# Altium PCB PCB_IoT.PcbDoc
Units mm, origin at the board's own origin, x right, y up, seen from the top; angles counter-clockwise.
Board outline 99 x 58 mm, 2 copper layers (Top Layer, Bottom Layer); 42 components, 35 nets, 208 pads, 0 vias.
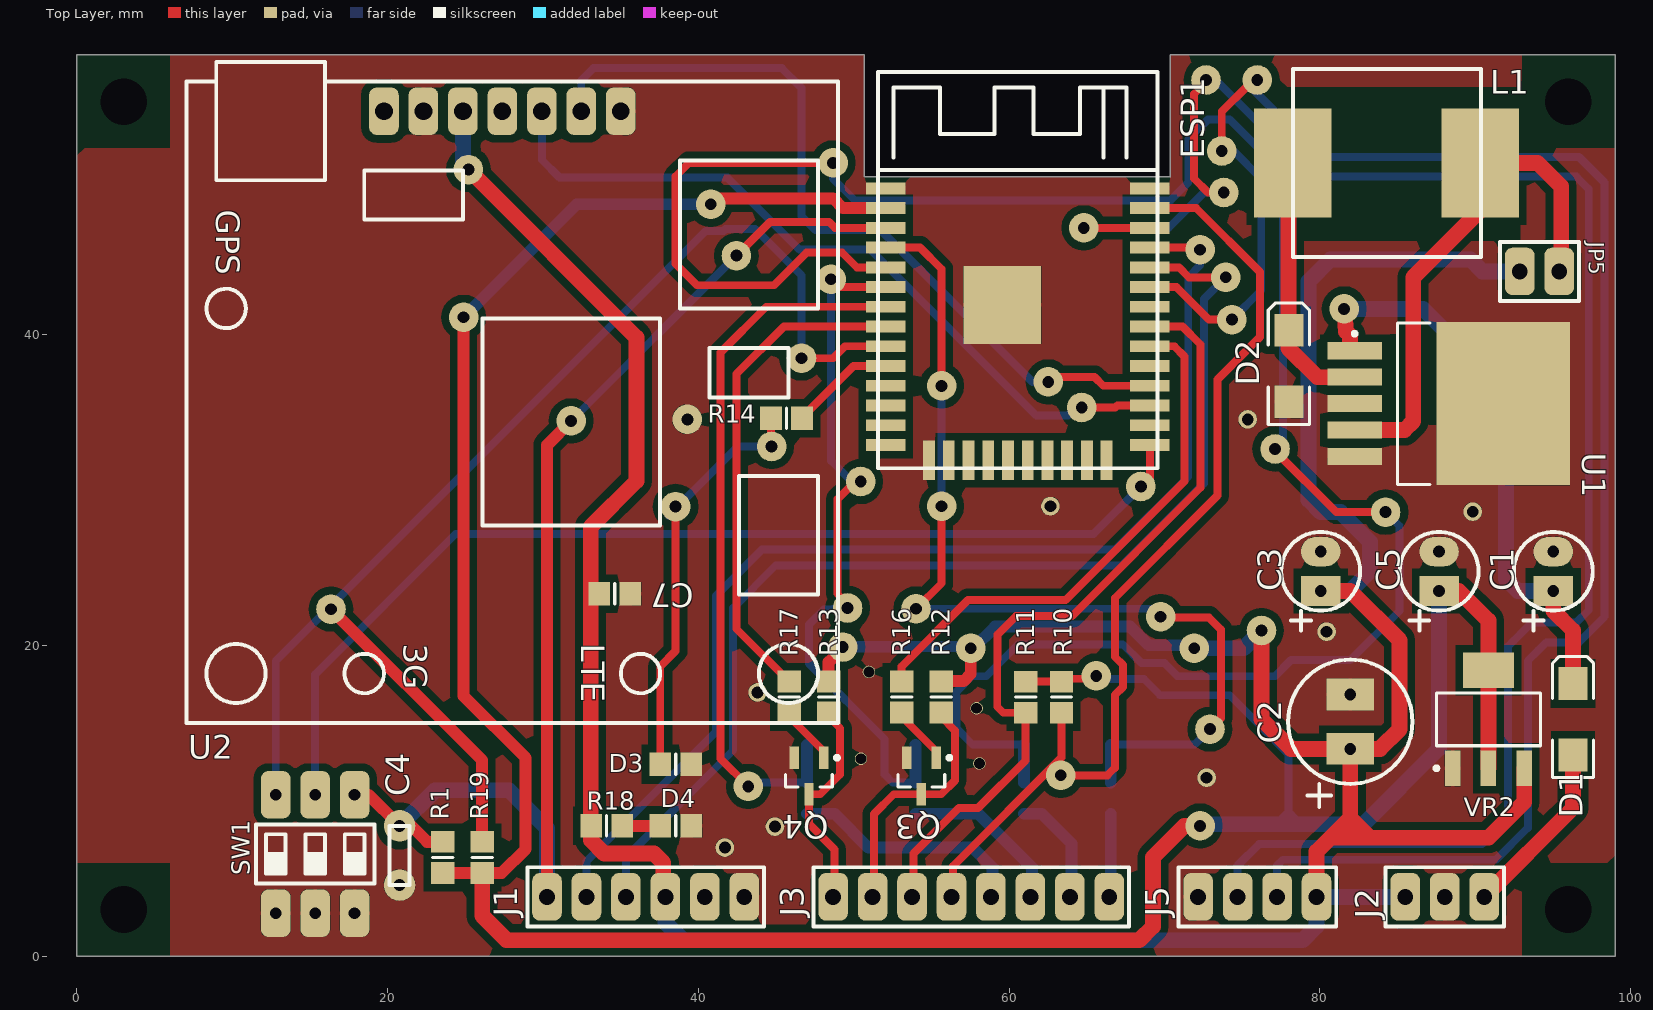
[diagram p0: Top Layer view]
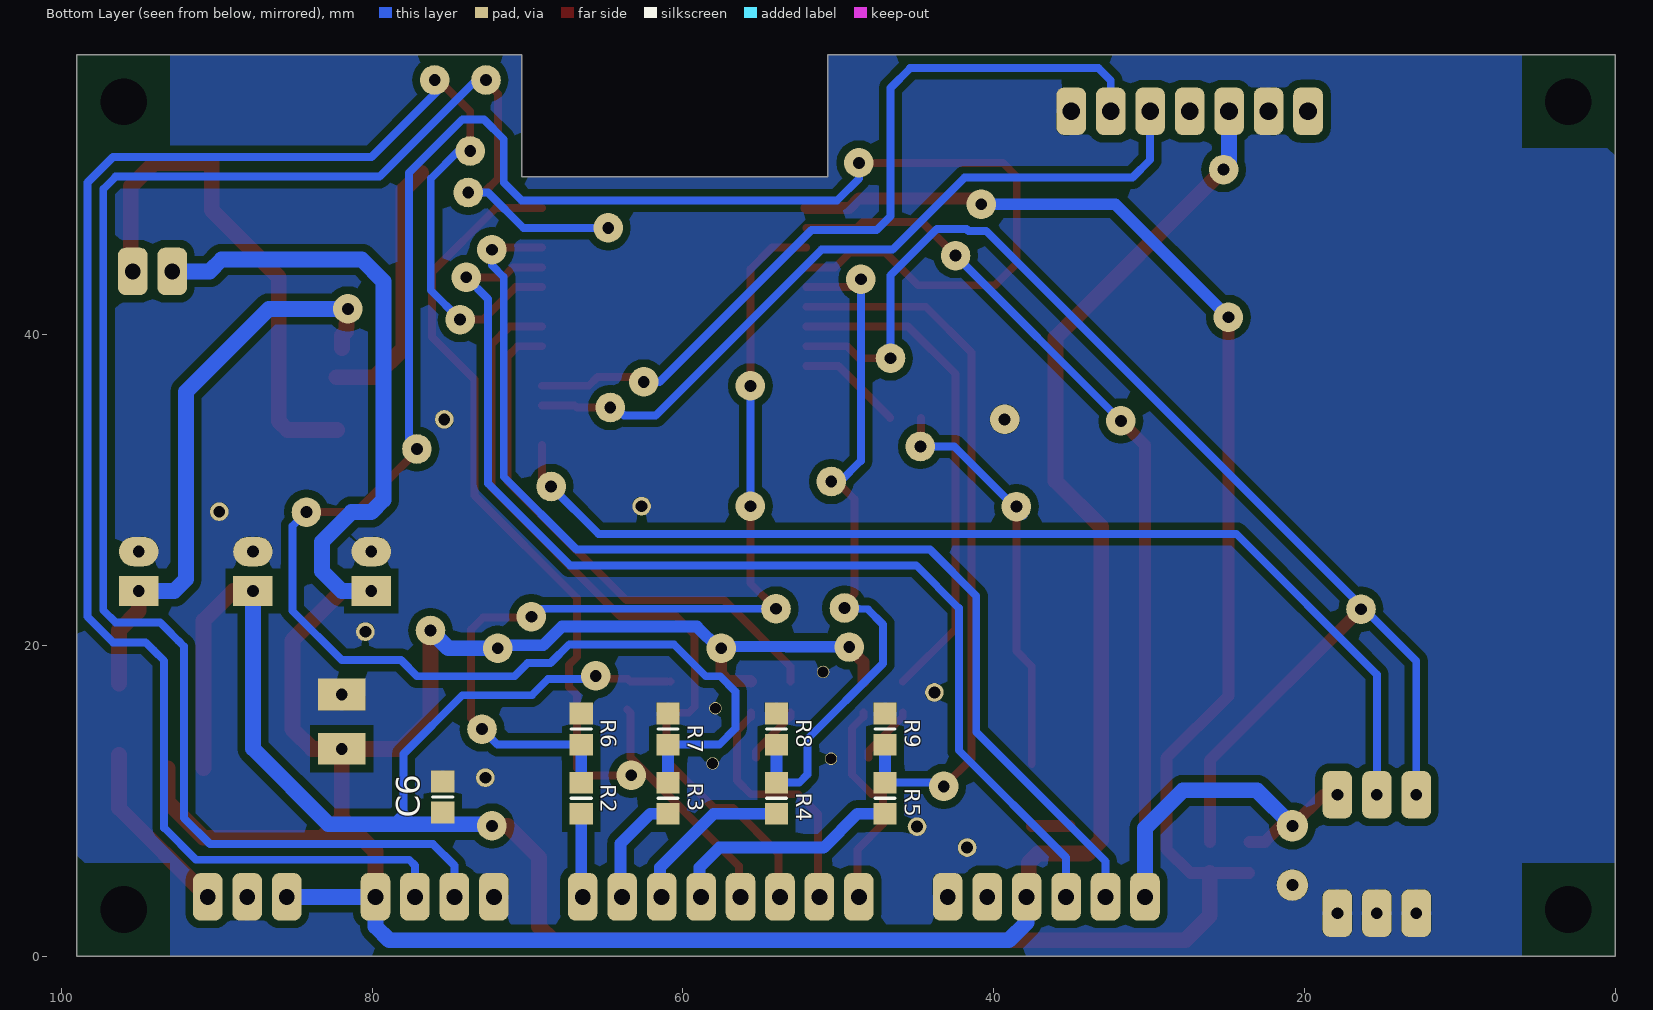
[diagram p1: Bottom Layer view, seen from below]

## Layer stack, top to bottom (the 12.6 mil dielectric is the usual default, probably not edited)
Top Solder: solder mask 0.0102, Solder Resist, Dk 3.5
Top Layer: signal copper 0.0356
Dielectric 1: dielectric 0.32, FR-4, Dk 4.8
Bottom Layer: signal copper 0.0356
Bottom Solder: solder mask 0.0102, Solder Resist, Dk 3.5

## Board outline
0,0 0,58 50.67,58 50.67,50.165 70.355,50.165 70.355,58 99,58 99,0

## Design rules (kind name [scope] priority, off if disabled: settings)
Clearance Clearance_4 [InNamedPolygon('GND_BOTTOM')] p1: gap=0.5 ignorepadtopadclearanceinfootprint=FALSE
Clearance Clearance_3 [InNamedPolygon('GND_TOP')] p2: gap=0.5 ignorepadtopadclearanceinfootprint=FALSE
Clearance Clearance_2 [InNamedPolygon('GND_BOTTOM')] p3: gap=0.5 ignorepadtopadclearanceinfootprint=FALSE
Clearance Clearance_1 [InNamedPolygon('GND_TOP')] p4: gap=0.5 ignorepadtopadclearanceinfootprint=FALSE
Clearance [All] p5: gap=0.508 ignorepadtopadclearanceinfootprint=FALSE
HoleSize [All] p1: absolutevalues=TRUE maxlimit=4 minlimit=0.025 maxpercent=80.000 minpercent=20.000
PolygonConnect PolygonConnect_4 [All vs IsNamedPolygon('GND_BOTTOM')] p1: connectstyle=Relief reliefconductorwidth=0.254 reliefentries=4 polygonreliefangle="90 Angle" airgapwidth=0
PolygonConnect PolygonConnect_3 [All vs IsNamedPolygon('GND_TOP')] p2: connectstyle=Relief reliefconductorwidth=0.254 reliefentries=4 polygonreliefangle="90 Angle" airgapwidth=0
PolygonConnect PolygonConnect_2 [All vs IsNamedPolygon('GND_BOTTOM')] p3: connectstyle=Relief reliefconductorwidth=0.254 reliefentries=4 polygonreliefangle="90 Angle" airgapwidth=0
PolygonConnect PolygonConnect_1 [All vs IsNamedPolygon('GND_TOP')] p4: connectstyle=Relief reliefconductorwidth=0.254 reliefentries=4 polygonreliefangle="90 Angle" airgapwidth=0
PolygonConnect [All] p5: connectstyle=Relief reliefconductorwidth=0.254 reliefentries=4 polygonreliefangle="90 Angle" airgapwidth=0.254
RoutingVias [All] p1: holewidth=0.711 width=1.27 viastyle="Through Hole" minholewidth=0.711 minwidth=1.27 maxholewidth=0.711 maxwidth=1.27
SilkToSilkClearance [All] p1 off: silktosilkclearance=0.254
SilkToSolderMaskClearance [IsPad] p1 off: minsilkscreentomaskgap=0.254 clearancetoexposedcopper=TRUE
SolderMaskExpansion [All] p1: expansion=0.102 istentingtop=FALSE
Width [All] p1: maxlimit=1.016 minlimit=0.508 preferedwidth=0.762
27 further rules are at their usual default settings.

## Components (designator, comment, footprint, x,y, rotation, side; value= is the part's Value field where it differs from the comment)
C1 "CAP_ELEC" CAP_ELEC_1 95.025,23.495 r90 top value=100uF/35V
C2 "CAP_ELEC" CAP_ELEC_3.5MM 81.96,13.335 r90 top value=220uF/35V
C3 "CAP_ELEC" CAP_ELEC_1 80.055,23.495 r90 top value=100uF/35V
C4 "Cap" CAP 20.765,4.57 r90 top value=100nF
C5 "Cap2" CAP_ELEC_1 87.675,23.495 r90 top value=100uF/35V
C6 "Cap" 6-0805_M 75.458,10.236 r270 bottom value=100nF
C7 "Cap" 6-0805_M 34.614,23.317 r180 top value=100nF
D1 "Diode 1N4007" DO214 96.295,15.24 r90 top
D2 "1N5822" DO214 78.007,37.973 r90 top
D3 "LED0" 6-0805_M 38.541,12.344 r0 top
D4 "LED0" 6-0805_M 38.541,8.382 r0 top
ESP1 "ESP-WROOM-32" ESP32-WROOM-32D 59.56,41.91 r0 top
J1 "SIL_6" SIL_6 42.955,3.81 r180 top
J2 "SIL_3" SIL_3 90.58,3.81 r180 top
J3 "SIL_8" SIL_8 66.45,3.81 r180 top
J5 "SIL_4" SIL_4 79.785,3.81 r180 top
JP5 "JUMPER" SIL_2 95.406,44.069 r180 top
L1 "Inductor" INDUTOR_SMD 78.261,51.054 r0 top value=33uH
Q3 "BC817-25" SOT-23A_M 54.353,11.589 r270 top
Q4 "BC817-25" SOT-23A_M 47.114,11.589 r270 top
R1 "Res1" 6-0805_M 23.54,6.35 r270 top value=22k
R2 "Res1" 6-0805_M 66.545,10.16 r270 bottom value=0R
R3 "Res1" 6-0805_M 60.957,10.16 r270 bottom value=0R
R4 "Res1" 6-0805_M 53.972,10.16 r270 bottom value=0R
R5 "Res1" 6-0805_M 46.987,10.16 r270 bottom value=0R
R6 "Res1" 6-0805_M 66.545,14.605 r270 bottom value=100k
R7 "Res1" 6-0805_M 60.957,14.605 r270 bottom value=100k
R8 "Res1" 6-0805_M 53.972,14.605 r270 bottom value=100k
R9 "Res1" 6-0805_M 46.987,14.605 r270 bottom value=100k
R10 "Res1" 6-0805_M 63.373,16.662 r270 top value=3k3
R11 "Res1" 6-0805_M 61.062,16.662 r270 top value=3k3
R12 "Res1" 6-0805_M 55.623,16.669 r270 top value=3k3
R13 "Res1" 6-0805_M 48.384,16.669 r270 top value=3k3
R14 "Res1" 6-0805_M 45.669,34.62 r180 top value=1K
R16 "Res1" 6-0805_M 53.083,16.669 r90 top value=3k3
R17 "Res1" 6-0805_M 45.844,16.669 r90 top value=3k3
R18 "Res1" 6-0805_M 34.096,8.382 r0 top value=1K
R19 "Res1" 6-0805_M 26.08,6.35 r270 top value=10K
SW1 "DIP_SWITCH_3" DIP_6 12.793,2.76 r0 top
U1 "LM2596S-5.0" TS5B_M 88.294,35.56 r0 top
U2 "SIM7600" Modulo_SIM7600SA 19.761,54.381 r0 top
VR2 "AMS1117 3.3" SOT-223B_M 90.85,15.24 r90 top

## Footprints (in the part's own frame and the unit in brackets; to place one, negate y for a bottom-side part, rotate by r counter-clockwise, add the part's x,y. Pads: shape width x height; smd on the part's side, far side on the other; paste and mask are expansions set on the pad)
6-0805_M [mm] "Chip Resistor, Body 2.0x1.2mm, IPC Low Density"
  rect 1.4x1.5 smd: 1(-1,0) 2(1,0)
  silkscreen extent 0,-0.65 0,0.65, body extent -1.07,-0.7 1.07,0.7, height 0.7
CAP [mil] "CAP"
  round 80 hole 30: 1(0,0) 2(150,0)
  silkscreen extent 0,-25 150,25
CAP_ELEC_1 [mil] "CAP_ELEC_1"
  rect 75x100 hole 30: 1(0,0)
  oval 75x100 hole 30: 2(100,0)
  silkscreen extent -100,-100 150,100
CAP_ELEC_3.5MM [mil] "CAP_ELEC_3.5MM"
  rect 80x120 hole 30: 1(0,0) 2(137.8,0)
  silkscreen extent -148,-157 226,157
DIP_6 [mil] "DIP_6"
  rrect50% 75x120 hole 30: 1(0,0) 2(100,0) 3(200,0) 4(200,300) 5(100,300) 6(0,300)
  silkscreen extent -50,75 250,225
DO214 [mm] "DO-214-AC/SMA; 2 C-Bend Leads; Body 5.3 x 2.6 mm, inc. leads (LxW)"
  rect 2.1x1.85 smd: 1(-2.3,0) 2(2.3,0)
  silkscreen extent -3.75,-1.33 4.05,1.33
ESP32-WROOM-32D [mm]
  rect 2.54x0.762 smd: 1(-7.5,7.5) 2(-7.5,6.23) 3(-7.5,4.96) 4(-7.5,3.69) 5(-7.5,2.42) 6(-7.5,1.15) 7(-7.5,-0.12) 8(-7.5,-1.39) 9(-7.5,-2.66) 10(-7.5,-3.93) 11(-7.5,-5.2) 12(-7.5,-6.47) 13(-7.5,-7.74) 14(-7.5,-9.01) 25(9.5,-9.01) 26(9.5,-7.74) 27(9.5,-6.47) 28(9.5,-5.2) 29(9.5,-3.93) 30(9.5,-2.66) 31(9.5,-1.39) 32(9.5,-0.12) 33(9.5,1.15) 34(9.5,2.42) 35(9.5,3.69) 36(9.5,4.96) 37(9.5,6.23) 38(9.5,7.5)
  rect 0.762x2.54 smd: 15(-4.715,-10.01) 16(-3.445,-10.01) 17(-2.175,-10.01) 18(-0.905,-10.01) 19(0.365,-10.01) 20(1.635,-10.01) 21(2.905,-10.01) 22(4.175,-10.01) 23(5.445,-10.01) 24(6.715,-10.01)
  rect 5x5 smd: 39(0,0)
  silkscreen extent -8,-10.51 10,14.99
INDUTOR_SMD [mm] "INDUTOR_SMD"
  rect 5x7 smd: 1(0,0) 2(12.07,0)
  silkscreen extent 0,-6.05 12.1,6.05
Modulo_SIM7600SA [mil] "Modulo_SIM7600SA"
  rrect50% 75x120 hole 45: 1(600,0) 2(500,0) 3(400,0) 4(300,0) 5(200,0) 6(100,0) 7(0,0)
  silkscreen extent -500,-1550 1150,125
SIL_2 [mil] "SIL_2"
  rrect50% 75x120 hole 40: 1(0,0) 2(100,0)
  silkscreen extent -50,-75 150,75
SIL_3 [mil] "SIL_3"
  rrect50% 75x120 hole 40: 1(0,0) 2(100,0) 3(200,0)
  silkscreen extent -50,-75 250,75
SIL_4 [mil] "SIL_4"
  rrect50% 75x120 hole 40: 1(0,0) 2(100,0) 3(200,0) 4(300,0)
  silkscreen extent -50,-75 350,75
SIL_6 [mil] "SIL_6"
  rrect50% 75x120 hole 40: 1(0,0) 2(100,0) 3(200,0) 4(300,0) 5(400,0) 6(500,0)
  silkscreen extent -50,-75 550,75
SIL_8 [mil] "SIL_8"
  rrect50% 75x120 hole 40: 1(0,0) 2(100,0) 3(200,0) 4(300,0) 5(400,0) 6(500,0) 7(600,0) 8(700,0)
  silkscreen extent -50,-75 750,75
SOT-23A_M [mm] "SOT23, 3-Leads, Body 2.9x1.3mm, Pitch 0.95mm, Lead Span 2.3mm, IPC Low Density"
  rect 1.45x0.6 smd: 1(-1.175,0.95) 2(-1.175,-0.95) 3(1.175,0)
  silkscreen extent -1.3,-1.5 0.7,1.93, body extent -0.7,-1.5 0.7,1.5, height 1.09
SOT-223B_M [mm] "SOT223, 4-Leads, Body 6.5x3.5mm, Pitch 2.3mm, Lead Span 7mm, IPC Low Density"
  rect 2.3x1 smd: 1(-3.15,2.3) 2(-3.15,0) 3(-3.15,-2.3)
  rect 2.3x3.3 smd: 4(3.15,0)
  silkscreen extent -3.27,-3.35 1.7,3.47, body extent -1.85,-3.35 1.85,3.35, height 1.8
TS5B_M [mm] "D2-PAK, 6-Leads, Body 8.6x10.2mm, Pitch 1.7mm, Lead Span 14.1mm, IPC Low Density"
  rect 3.5x1.1 smd: 1(-6.05,3.4) 2(-6.05,1.7) 3(-6.05,0) 4(-6.05,-1.7) 5(-6.05,-3.4)
  rect 8.6x10.5 smd: 6(3.5,0)
  silkscreen extent -6.17,-5.2 -1.2,5.2, body extent -3.3,-5.2 6.1,5.2, height 4.65

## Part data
C1 C2 C3: "Capacitor eletrolitico radial"
C4 C5 C6 C7: "Capacitor"
D1: "1 Amp General Purpose Rectifier"
D3 D4: "Typical INFRARED GaAs LED"
J3: "SIL 8 Connector"
Q3 Q4: "NPN General Purpose Amplifier"
R1 R2 R3 R4 R5 R6 R7 R8 R9 R10 R11 R12 R13 R14 R16 R17 R18 R19: "Resistor"
SW1: "DIP SWITCH 3 WAYS"
U1: "SIMPLE SWITCHER® Power Converter 150 KHz 3A Step-Down Voltage Regulator, 5-pin TO-263", Manufacturer="National Semiconductor", PackageTopMarking="NSUZXYTTE#*LM2596S*-5.0 P+", PowerWise=N, Supplier Part Number 1=1214546
U2: library part Modulo_SIM7600
VR2: library part "Volt Reg", "Voltage Regulator"

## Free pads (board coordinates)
  round 1.905 hole 0.762: 59(49.296,19.888) 60(57.531,19.812) 63(71.911,19.812) 65(72.292,45.466) 66(73.943,43.688) 67(42.447,45.085) 68(46.638,38.481) 69(81.563,41.656) 72(64.672,35.306) 73(62.513,36.957) 74(68.482,30.226) 80(43.209,10.922) 81(38.532,28.931) 81(44.714,32.801) 81(49.6,22.403) 82(50.448,30.543) 83(48.543,43.561) 84(84.23,28.575) 85(77.118,32.639) 86(48.67,51.054) 87(40.796,48.387) 89(74.34,40.966) 91(73.689,51.816) 93(75.975,56.388) 94(64.806,46.87) 95(73.816,49.149) 96(72.673,56.388) 97(55.655,36.703) 98(55.655,28.956) 100(54.004,22.352) 101(63.322,11.633) 101(65.608,18.034) 101(69.752,21.844) 102(72.927,14.605) 104(72.292,8.382) 109(39.288,34.544) 117(76.245,20.955) 118(31.81,34.448) 119(24.889,41.116) 120(16.352,22.327) 122(25.197,50.622)
  round 1.905 hole 3: 64(3,3) 64(3,55) 64(96,3) 64(96,55)
  round 1.2 hole 0.762: 106(41.701,6.985) 108(62.656,28.956) 108(75.356,34.544) 112(44.927,8.331) 113(43.809,16.967) 115(80.436,20.879) 116(72.714,11.481) 116(89.84,28.6)
  round 0.8 hole 0.7: 106(50.464,12.7) 106(50.972,18.288) 106(57.906,15.951) 106(58.084,12.395)

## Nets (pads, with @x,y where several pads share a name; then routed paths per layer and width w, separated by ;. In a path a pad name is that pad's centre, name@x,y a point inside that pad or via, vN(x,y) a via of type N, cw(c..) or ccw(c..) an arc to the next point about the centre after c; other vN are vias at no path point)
+3.3V: C5.1 C6.2 ESP1.2 pad.87 pad.101@65.608,18.034 pad.104 pad.119 R1.2 R10.1 R11.1 R19.2 VR2.2 VR2.4 | length 195.2
  Top Layer w0.508: R11.1@60.808,17.662 R11.1@60.811,17.666 ; R11.1 R10.1 63.559,17.848 65.422,17.848 pad.101@65.608,18.034 ; pad.104@72.025,8.649 pad.104
  Top Layer w0.762: R1.2 R19.2 27.341,5.35 28.874,6.883 28.874,12.751 24.889,16.736 pad.119 ; pad.87 41.177,48.768 48.67,48.768 49.298,48.14 ESP1.2
  Top Layer w1.016: R19.2 26.08,2.591 27.655,1.016 68.371,1.016 69.26,1.905 69.26,6.35 71.292,8.382 pad.104 ; C5.1@87.532,23.495 C5.1 88.945,23.495 90.85,21.59 VR2.4 VR2.2
  Bottom Layer w0.508: pad.101@65.608,18.034 65.799,17.843 68.669,17.843 69.723,16.789 74.193,16.789 77.978,13.005 77.978,9.271 ; 77.013,8.484 77.191,8.484 77.978,9.271 ; 78.207,8.484 77.978,8.712 77.978,9.271 ; 78.486,8.763 77.978,9.271 ; 78.765,8.484 79.045,8.484
  Bottom Layer w0.762: pad.119 32.16,48.387 pad.87
  Bottom Layer w1.016: pad.104 72.394,8.484 77.013,8.484 ; 77.191,8.484 78.207,8.484 78.765,8.484 82.804,8.484 87.675,13.355 C5.1
+5V: C2.1 C3.1 C7.2 J1.3 J2.3 J5.1 JP5.2 pad.59 pad.60 pad.63 pad.117 pad.122 R12.1 R13.1 R18.1 U2.5 VR2.3 | length 244
  Top Layer w0.762: R13.1 48.384,18.923 49.273,19.812 pad.59 ; R12.1 55.657,17.703 57.07,17.703 57.531,18.164 pad.60 ; pad.63@71.911,19.415 pad.63
  Top Layer w1.016: pad.122 36.011,39.808 36.011,30.582 33.065,27.635 33.065,7.473 33.944,6.595 37.149,6.595 37.744,5.999 37.744,3.941 J1.3 ; pad.117 76.245,15.24 78.15,13.335 C2.1 ; J5.1 79.785,6.731 79.801,6.731 80.69,7.62 ; C3.1 81.96,23.495 85.135,20.32 85.135,14.605 83.865,13.335 C2.1 ; VR2.3 93.15,9.92 90.85,7.62 83.23,7.62 ; 80.69,7.62 81.96,7.62 ; 80.69,7.62 81.96,8.89 ; 81.96,7.62 83.23,7.62 ; 81.96,7.62 81.96,8.89 ; 81.96,8.89 83.23,7.62 ; 81.96,8.89 C2.1
  Bottom Layer w0.762: pad.59 pad.60@57.53,19.937 ; pad.60 57.7,19.812 59.097,21.209 67.783,21.209 68.989,20.002 71.721,20.002 pad.63
  Bottom Layer w1.016: U2.5 24.841,50.978 pad.122 ; J1.3 37.875,2.159 39.018,1.016 78.896,1.016 79.785,1.905 J5.1 J2.3 ; pad.63 75.102,19.812 pad.117 ; C3.1 81.96,23.495 83.23,24.765 83.23,26.67 81.325,28.575 80.055,28.575 79.277,29.353 79.277,43.434 80.674,44.831 89.691,44.831 90.453,44.069 JP5.2
+24V: D1.1 J2.1 | length 11.5
  Top Layer w1.016: J2.1 96.295,9.525 D1.1
AN1: ESP1.4 pad.97 pad.98 pad.100 pad.101@69.752,21.844 pad.102 R2.1 R6.2 | length 63.4
  Top Layer w0.508: ESP1.4 54.267,45.6 55.655,44.212 pad.97 pad.97@55.655,36.449 ; pad.100 55.655,24.003 pad.98 ; pad.101@69.752,21.844 69.752,21.78 72.864,21.78 73.626,21.018 73.626,15.303 pad.102
  Bottom Layer w0.508: pad.100 69.244,22.352 pad.101@69.752,21.844 ; pad.98@55.655,28.702 pad.98 pad.97 ; R6.2 71.927,13.605 pad.102
  Bottom Layer w0.762: R2.1 R6.2
AN2: ESP1.5 pad.84 pad.85 pad.86 R3.1 R7.2 | length 142.8
  Top Layer w0.508: pad.86 39.399,51.054 38.51,50.165 38.51,44.577 39.907,43.18 44.86,43.18 46.956,45.276 49.253,45.276 50.199,44.33 ESP1.5 ; pad.85 77.118,32.512 81.055,28.575 pad.84
  Bottom Layer w0.508: pad.86 48.67,50.038 50.067,48.641 70.387,48.641 71.53,49.784 71.53,52.578 72.8,53.848 74.197,53.848 77.626,50.419 77.626,33.274 pad.85 ; R7.2 57.662,13.605 56.611,14.656 56.611,17.018 57.601,18.009 58.522,18.009 60.579,20.066 67.309,20.066 68.516,18.86 69.99,18.86 70.841,18.009 77.109,18.009 78.15,19.05 81.96,19.05 85.135,22.225 85.135,27.67 pad.84
  Bottom Layer w0.762: R3.1 R7.2
AN3: ESP1.6 pad.81@49.6,22.403 pad.82 pad.83 R4.1 R8.2 | length 46.2
  Top Layer w0.508: pad.83 49.044,43.06 ESP1.6 ; pad.81@49.6,22.403 48.965,23.326 48.965,29.413 50.096,30.543 pad.82
  Bottom Layer w0.508: pad.83 48.543,31.877 49.877,30.543 pad.82 ; pad.81@49.6,22.403 48.096,22.321 47.111,21.336 47.111,18.831 51.988,13.954 51.988,11.684 52.512,11.16 R4.1
  Bottom Layer w0.762: R4.1 R8.2
AN4: ESP1.7 pad.80 R5.1 R9.2 | length 46.9
  Top Layer w0.508: pad.80 41.427,12.704 41.427,38.842 44.375,41.79 ESP1.7
  Bottom Layer w0.508: pad.80@43.082,11.176 43.098,11.16 R5.1
  Bottom Layer w0.762: R5.1 R9.2
DO3: ESP1.30 R16.2 | length 34.6
  Top Layer w0.508: R16.2 53.083,18.637 57.357,22.911 63.638,22.911 71.292,30.565 71.292,38.592 70.634,39.25 ESP1.30
DO4: ESP1.8 R17.2 | length 32.1
  Top Layer w0.508: R17.2 42.443,21.07 42.443,37.461 45.502,40.52 ESP1.8
EN: C4.2 ESP1.3 J1.6 pad.67 pad.118 R1.1 SW1.4 | length 79.8
  Top Layer w0.508: J1.6 J1.6@30.255,4.664 ; pad.67 44.606,47.244 48.416,47.244 48.79,46.87 ESP1.3
  Top Layer w0.762: SW1.4 18.765,10.38 C4.2 21.51,8.38 22.54,7.35 R1.1 ; J1.6@30.255,4.664 30.255,32.893 pad.118
  Bottom Layer w0.508: pad.118 pad.67
  Bottom Layer w1.016: C4.2 23.053,10.668 27.807,10.668 30.255,8.22 J1.6
GND: C1.2 C2.2 C3.2 C4.1 C5.2 C6.1 C7.1 D2.1 D3.2 D4.2 ESP1.1 ESP1.15 ESP1.38 ESP1.39 J1.1 J2.2 J5.4 pad.106 pad.108 pad.109 pad.112 pad.113 pad.115 pad.116 Q3.2 Q4.2 R6.1 R7.1 R8.1 R9.1 SW1.1 SW1.2 SW1.3 U1.3 U1.5 U1.6 U2.1 U2.6 VR2.1
IN1: J3.1 R2.2 | length 5.3
  Bottom Layer w0.762: J3.1@66.545,3.81 R2.2
IN2: J3.2 R3.2 | length 7.3
  Bottom Layer w0.762: R3.2 62.1,9.16 64.005,7.255 J3.2@64.005,3.81
IN3: J3.3 R4.2 | length 10.8
  Bottom Layer w0.762: R4.2 58.02,9.16 61.465,5.715 J3.3@61.465,3.81
IN4: J3.4 R5.2 | length 15.3
  Bottom Layer w0.762: R5.2 48.765,9.16 50.94,6.985 57.655,6.985 58.925,5.715 J3.4@58.925,3.81
IN5: ESP1.37 J3.5 pad.101@63.322,11.633 R10.2 | length 63.7
  Top Layer w0.508: J3.5@56.385,3.81 56.395,3.82 56.395,5.798 63.373,12.776 R10.2 R10.2@63.581,15.87 ; pad.101@63.322,11.633 66.319,11.633 66.802,12.116 66.802,16.803 67.323,17.324 67.323,18.744 66.802,19.265 66.802,23.038 73.406,29.642 73.406,37.109 76.149,39.853 76.149,44.033 72.043,48.14 ESP1.37
IN6: ESP1.31 J3.6 R11.2 | length 52.1
  Top Layer w0.508: J3.6@53.845,3.81 53.845,6.604 56.766,9.525 57.996,9.525 61.062,12.59 R11.2 59.623,15.662 59.233,16.053 59.233,19.089 59.245,19.102 59.245,20.688 60.452,21.895 64.059,21.895 72.308,30.144 72.308,39.376 71.164,40.52 ESP1.31
IO0: ESP1.25 pad.74 SW1.5 | length 68.8
  Top Layer w0.508: pad.74 69.06,30.804 ESP1.25
  Bottom Layer w0.508: SW1.5 15.333,18.127 24.384,27.178 65.434,27.178 pad.74
LED1: ESP1.10 R14.1 | length 6.8
  Top Layer w0.508: R14.1 46.669,34.67 49.979,37.98 ESP1.10
MODE: ESP1.9 pad.68 pad.120 R19.1 SW1.6 | length 85.3
  Top Layer w0.508: pad.68 48.67,38.481 49.439,39.25 ESP1.9
  Top Layer w0.762: pad.120 26.08,12.598 R19.1
  Bottom Layer w0.508: SW1.6 12.793,18.987 40.479,46.672 41.61,46.672 41.737,46.799 43.654,46.799 46.638,43.815 pad.68
NetC1_1: C1.1 D1.2 pad.69 U1.1 | length 37.2
  Top Layer w1.016: pad.69 81.69,40.205 81.944,39.951 U1.1@81.944,39.116 ; C1.1 95.025,22.225 96.295,20.955 D1.2
  Bottom Layer w1.016: pad.69 86.643,41.656 91.977,36.322 91.977,24.257 92.739,23.495 C1.1
NetD2_2: D2.2 L1.1 U1.2 | length 16.8
  Top Layer w1.016: L1.1@76.864,50.419 77.975,49.308 77.975,39.13 79.845,37.26 U1.2 U1.2@82.3,37.26
NetD3_1: D3.1 pad.81@38.532,28.931 pad.81@44.714,32.801 R14.2 | length 27.6
  Top Layer w0.508: D3.1 37.541,18.644 38.532,19.634 pad.81@38.532,28.931 ; R14.2 44.669,32.547 pad.81@44.704,32.512
  Bottom Layer w0.508: pad.81@38.075,28.346 42.529,32.801 pad.81@44.714,32.801
NetD4_1: D4.1 R18.2 | length 2.4
  Top Layer w0.762: R18.2 D4.1
NetJP5_1: JP5.1 L1.2 U1.4 | length 33.8
  Top Layer w1.016: U1.4 85.451,33.86 86.008,34.417 86.008,43.688 90.331,48.011 L1.2 94.009,51.054 95.533,49.53 95.533,44.196 JP5.1
NetQ3_1: Q3.1 R16.1 | length 3.8
  Top Layer w0.508: R16.1 53.083,15.399 55.303,13.179 Q3.1
NetQ4_1: Q4.1 R17.1 | length 3.8
  Top Layer w0.508: R17.1 45.844,15.399 48.064,13.179 Q4.1
OUT3: J3.7 Q3.3 R12.2 | length 16.2
  Top Layer w0.508: J3.7@51.305,3.81 51.305,9.144 52.575,10.414 Q3.3 55.623,10.414 56.512,11.303 56.512,14.51 55.623,15.399 R12.2
OUT4: J3.8 Q4.3 R13.2 | length 14.1
  Top Layer w0.508: R13.2 48.384,15.399 49.126,14.657 49.126,11.696 47.844,10.414 Q4.3 47.114,8.509 48.765,6.858 J3.8@48.765,3.81
RXD0: ESP1.34 J1.4 pad.66 | length 74.1
  Top Layer w0.508: ESP1.34 70.928,44.33 71.57,43.688 pad.66
  Bottom Layer w0.508: J1.4 35.335,6.35 42.234,13.249 42.234,22.393 44.987,25.146 67.264,25.146 72.546,30.428 72.546,42.291 pad.66
RXD2: ESP1.27 pad.72 U2.3 | length 49
  Top Layer w0.508: pad.72 66.831,35.306 66.965,35.44 ESP1.27
  Bottom Layer w0.508: U2.3 29.921,51.257 31.064,50.114 41.863,50.114 46.511,45.466 51.083,45.466 61.751,34.798 63.783,34.798 pad.72@64.291,35.306
SCL: ESP1.36 J5.3 pad.94 pad.95 pad.96 | length 116.3
  Top Layer w0.508: pad.94@64.799,46.863 pad.94 ESP1.36 ; pad.96@72.8,56.388 71.911,55.499 71.911,50.038 72.8,49.149 pad.95
  Bottom Layer w0.508: pad.94 70.267,46.87 72.546,49.149 pad.95 ; pad.96 73.308,56.388 79.531,50.165 96.509,50.165 97.311,49.363 97.311,22.265 96.509,21.463 93.644,21.463 92.12,19.939 ; J5.3 74.705,5.826 76.093,7.214 79.395,7.214 90.444,7.214 92.12,8.89 92.12,19.939 ; 92.501,20.32 92.12,19.939
SDA: ESP1.33 J5.2 pad.89 pad.91 pad.93 | length 114.5
  Top Layer w0.508: ESP1.33 70.761,43.06 72.855,40.966 pad.89 ; pad.91 73.689,54.356 pad.93@75.34,56.007
  Bottom Layer w0.508: pad.91 74.451,51.816 76.229,50.038 76.229,42.855 pad.89 ; pad.93@75.467,56.007 80.039,51.435 96.676,51.435 98.327,49.784 98.327,21.844 96.676,20.193 94.584,20.193 93.39,18.999 ; J5.2 77.245,5.826 77.617,6.198 80.588,6.198 91.333,6.198 93.39,8.255 93.39,18.999 ; 94.05,19.66 93.39,18.999
TXD0: ESP1.35 J1.5 pad.65 | length 75.1
  Top Layer w0.508: ESP1.35 pad.65@72.8,45.6
  Bottom Layer w0.508: J1.5 32.795,6.096 41.117,14.418 41.117,23.181 44.098,26.162 66.843,26.162 71.53,30.849 71.53,43.7 72.292,44.462 pad.65
TXD2: ESP1.28 pad.73 U2.2 | length 52.5
  Top Layer w0.508: pad.73 62.831,37.274 65.498,37.274 66.062,36.71 ESP1.28
  Bottom Layer w0.508: U2.2 32.461,56.363 33.249,57.15 45.368,57.15 46.638,55.88 46.638,47.625 47.527,46.736 51.718,46.736 61.497,36.957 pad.73
pads on no net: ESP1.11 ESP1.12 ESP1.13 ESP1.14 ESP1.16 ESP1.17 ESP1.18 ESP1.19 ESP1.20 ESP1.21 ESP1.22 ESP1.23 ESP1.24 ESP1.26 ESP1.29 ESP1.32 J1.2 U2.4 U2.7

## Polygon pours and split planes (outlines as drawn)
GND on Top Layer "GND_TOP" (solid, pour order 0): 0,0 0,58 50.67,58 50.67,50.165 70.355,50.165 70.355,58 99,58 99,0
GND on Bottom Layer "GND_BOTTOM" (solid, pour order 1): 0,0 0,58 50.67,58 50.67,50.165 70.355,50.165 70.355,58 99,58 99,0

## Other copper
Top Layer:
  pour cut-out: 75.585,45.999 75.585,55.956 92.933,55.956 92.933,45.999
Multi-Layer:
  pour cut-out: 0,52 0,58 6,58 6,52
  pour cut-out: 93,52 93,58 99,58 99,52
  pour cut-out: 93,0 93,6 99,6 99,0
  pour cut-out: 0,0 0,6 6,6 6,0

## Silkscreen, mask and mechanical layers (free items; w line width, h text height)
Mechanical 1:
  lines w0.254: 0,0 99,0 99,58 70.355,58 70.355,50.165 50.67,50.165 50.67,58 49.185,58 0,58 0,0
